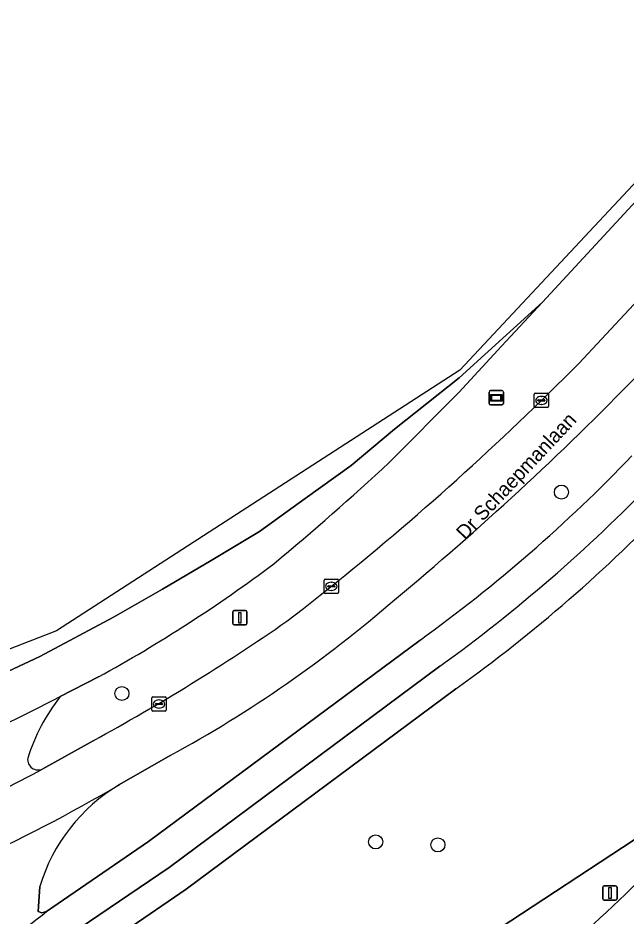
# Model space of a CAD drawing. Extents: x 161402 to 161933, y 381647 to 382315.
# Drawn here: x 161645 to 161687.4, y 382153.9 to 382216.4 of the extents above; entities that cross this region are included whole.
import ezdxf

# ---------------------------------------------------------------- set-up
doc = ezdxf.new("R2010")
doc.units = 0
for name, color, linetype in [('IMGEO_Berm_groen', 7, 'Continuous'), ('IMGEO_Boom', 7, 'Continuous'), ('IMGEO_Fietspad_open', 7, 'Continuous'), ('IMGEO_Groenvoorziening', 7, 'Continuous'), ('IMGEO_Kolk', 7, 'Continuous'), ('IMGEO_Lichtmast', 7, 'Continuous'), ('IMGEO_Openbare_ruimte_label', 7, 'Continuous'), ('IMGEO_Reclamebord', 7, 'Continuous'), ('IMGEO_Rijbaan_lokaal_gesloten', 7, 'Continuous'), ('IMGEO_Rijbaan_lokaal_open', 7, 'Continuous'), ('IMGEO_Voetpad_open', 7, 'Continuous')]:
    doc.layers.add(name, color=color, linetype=linetype)

msp = doc.modelspace()

# ---------------------------------------------------------------- linework, layer by layer
at = {"layer": 'IMGEO_Berm_groen'}
for points in [[(161689.496, 382205.269), (161681.527, 382196.651), (161678.676, 382193.568), (161675.69, 382190.338), (161670.839, 382185.46)], [(161681.452, 382189.793), (161684.055, 382192.367), (161693.624, 382202.616)], [(161646.478, 382155.909), (161646.374, 382154.17), (161646.623, 382154.084), (161646.957, 382154.172), (161654.067, 382159.041), (161672.989, 382173.086)], [(161650.566, 382170.516), (161647.909, 382169.155)], [(161646.692, 382164.118), (161650.189, 382166.07)], [(161655.565, 382165.041), (161652.03, 382163.012)]]:
    msp.add_lwpolyline(points, dxfattribs=at)
for centre, radius, start, end in [((161535.498, 382339.885), 212.859, 309.61126, 315.82773), ((161541.345, 382333.441), 200.661, 307.57252, 314.28499), ((161610.052, 382260.44), 107.665, 305.77231, 316.20072), ((161533.926, 382333.423), 201.589, 309.7406, 312.77852), ((161600.847, 382261.015), 103.257, 298.7838, 306.87243), ((161613.695, 382242.064), 87.667, 298.52876, 311.00082), ((161580.781, 382293.765), 145.339, 298.52599, 304.78691), ((161658.535, 382160.777), 13.531, 141.74802, 162.44396), ((161646.362, 382164.772), 0.733, 173.18463, 296.80226), ((161658.433, 382152.286), 12.492, 120.83452, 163.14016)]:
    msp.add_arc(centre, radius, start, end, dxfattribs=at)
at = {"layer": 'IMGEO_Boom'}
for centre in [(161682.85, 382183.401), (161652.204, 382169.365), (161669.896, 382159.022), (161674.234, 382158.814)]:
    msp.add_circle(centre, 0.489, dxfattribs=at)
at = {"layer": 'IMGEO_Fietspad_open'}
for points in [[(161672.989, 382173.086), (161654.067, 382159.041), (161646.957, 382154.172)], [(161641.929, 382148.646), (161647.103, 382151.551), (161647.127, 382151.564), (161655.489, 382157.231), (161674.382, 382171.277)]]:
    msp.add_lwpolyline(points, dxfattribs=at)
for centre, radius, start, end in [((161610.052, 382260.44), 107.665, 305.77231, 316.20072), ((161609.744, 382261.017), 110.596, 305.76448, 315.97187), ((161630.931, 382173.607), 25.19, 294.34251, 309.50932)]:
    msp.add_arc(centre, radius, start, end, dxfattribs=at)
at = {"layer": 'IMGEO_Groenvoorziening'}
for points in [[(161689.483, 382157.477), (161691.391, 382159.25), (161699.134, 382166.682), (161703.606, 382170.992), (161702.903, 382171.726), (161702.299, 382171.22), (161695.415, 382165.448), (161687.926, 382159.17), (161678.507, 382152.98), (161678.638, 382150.976), (161676.296, 382149.1), (161669.4, 382148.169), (161664.367, 382144.903), (161668.17, 382139.043)], [(161675.495, 382169.693), (161656.68, 382155.718), (161648.28, 382149.971), (161648.519, 382149.653), (161649.489, 382148.283)], [(161668.17, 382139.043), (161664.367, 382144.903), (161669.4, 382148.169), (161676.296, 382149.1), (161678.638, 382150.976), (161678.507, 382152.98), (161687.926, 382159.17), (161695.415, 382165.448)]]:
    msp.add_lwpolyline(points, dxfattribs=at)
for centre, radius, start, end in [((161611.861, 382258.34), 109.122, 305.67199, 316.21436), ((161516.254, 382334.874), 247.948, 312.0848, 314.31888)]:
    msp.add_arc(centre, radius, start, end, dxfattribs=at)
at = {"layer": 'IMGEO_Kolk'}
for p, q in [((161680.954, 382189.368), (161680.954, 382190.22)), ((161681.029, 382190.294), (161681.881, 382190.294)), ((161681.955, 382190.22), (161681.955, 382189.368)), ((161681.213, 382189.788), (161681.213, 382189.8)), ((161681.651, 382189.751), (161681.253, 382189.751)), ((161681.256, 382189.837), (161681.654, 382189.837)), ((161681.442, 382190.074), (161681.467, 382190.074)), ((161681.697, 382189.8), (161681.697, 382189.788)), ((161681.881, 382189.294), (161681.029, 382189.294)), ((161681.465, 382189.514), (161681.44, 382189.514)), ((161666.303, 382176.409), (161666.303, 382177.261)), ((161666.378, 382177.335), (161667.23, 382177.335)), ((161666.791, 382177.115), (161666.816, 382177.115)), ((161667.304, 382177.261), (161667.304, 382176.409)), ((161666.562, 382176.829), (161666.562, 382176.841)), ((161667, 382176.792), (161666.602, 382176.792)), ((161666.605, 382176.878), (161667.003, 382176.878)), ((161666.814, 382176.555), (161666.789, 382176.555)), ((161667.046, 382176.841), (161667.046, 382176.829)), ((161667.23, 382176.335), (161666.378, 382176.335)), ((161654.29, 382168.208), (161654.29, 382169.06)), ((161654.365, 382169.134), (161655.217, 382169.134)), ((161654.778, 382168.914), (161654.803, 382168.914)), ((161655.291, 382169.06), (161655.291, 382168.208)), ((161654.549, 382168.628), (161654.549, 382168.64)), ((161654.987, 382168.591), (161654.589, 382168.591)), ((161654.592, 382168.677), (161654.99, 382168.677)), ((161654.801, 382168.354), (161654.776, 382168.354)), ((161655.033, 382168.64), (161655.033, 382168.628)), ((161655.217, 382168.134), (161654.365, 382168.134))]:
    msp.add_line(p, q, dxfattribs=at)
for points in [[(161680.954, 382189.368), (161680.954, 382190.22)], [(161681.029, 382190.294), (161681.881, 382190.294)], [(161681.955, 382190.22), (161681.955, 382189.368)], [(161681.881, 382189.294), (161681.029, 382189.294)], [(161666.303, 382176.409), (161666.303, 382177.261)], [(161666.378, 382177.335), (161667.23, 382177.335)], [(161667.304, 382177.261), (161667.304, 382176.409)], [(161667.23, 382176.335), (161666.378, 382176.335)], [(161654.29, 382168.208), (161654.29, 382169.06)], [(161654.365, 382169.134), (161655.217, 382169.134)], [(161655.291, 382169.06), (161655.291, 382168.208)], [(161655.217, 382168.134), (161654.365, 382168.134)]]:
    msp.add_lwpolyline(points, dxfattribs=at)
for centre, radius, start, end in [((161681.031, 382190.218), 0.0765, 91.55205, 178.44795), ((161681.031, 382190.218), 0.0765, 91.55205, 178.44795), ((161681.879, 382190.218), 0.0765, 1.55205, 88.44795), ((161681.879, 382190.218), 0.0765, 1.55205, 88.44795), ((161681.253, 382189.797), 0.0403, 85.87752, 175.75265), ((161681.25, 382189.787), 0.0366, 178.93798, 274.71019), ((161681.654, 382189.794), 0.043, 264.86636, 352.45326), ((161681.658, 382189.799), 0.0386, 1.73085, 96.63898), ((161681.031, 382189.37), 0.0765, 181.55205, 268.44795), ((161681.031, 382189.37), 0.0765, 181.55205, 268.44795), ((161681.879, 382189.37), 0.0765, 271.55205, 358.44795), ((161681.879, 382189.37), 0.0765, 271.55205, 358.44795), ((161666.38, 382177.259), 0.0765, 91.55205, 178.44795), ((161666.38, 382177.259), 0.0765, 91.55205, 178.44795), ((161667.228, 382177.259), 0.0765, 1.55205, 88.44795), ((161667.228, 382177.259), 0.0765, 1.55205, 88.44795), ((161666.602, 382176.838), 0.0403, 85.87752, 175.75265), ((161666.599, 382176.828), 0.0366, 178.93798, 274.71019), ((161667.003, 382176.835), 0.043, 264.86636, 352.45326), ((161667.007, 382176.84), 0.0386, 1.73085, 96.63898), ((161666.38, 382176.411), 0.0765, 181.55205, 268.44795), ((161666.38, 382176.411), 0.0765, 181.55205, 268.44795), ((161667.228, 382176.411), 0.0765, 271.55205, 358.44795), ((161667.228, 382176.411), 0.0765, 271.55205, 358.44795), ((161654.367, 382169.058), 0.0765, 91.55205, 178.44795), ((161654.367, 382169.058), 0.0765, 91.55205, 178.44795), ((161655.215, 382169.058), 0.0765, 1.55205, 88.44795), ((161655.215, 382169.058), 0.0765, 1.55205, 88.44795), ((161654.589, 382168.637), 0.0403, 85.87752, 175.75265), ((161654.586, 382168.627), 0.0366, 178.93798, 274.71019), ((161654.99, 382168.634), 0.043, 264.86636, 352.45326), ((161654.994, 382168.639), 0.0386, 1.73085, 96.63898), ((161654.367, 382168.21), 0.0765, 181.55205, 268.44795), ((161654.367, 382168.21), 0.0765, 181.55205, 268.44795), ((161655.215, 382168.21), 0.0765, 271.55205, 358.44795), ((161655.215, 382168.21), 0.0765, 271.55205, 358.44795)]:
    msp.add_arc(centre, radius, start, end, dxfattribs=at)
for centre, major_axis, ratio, start_param, end_param in [((161681.441, 382189.794), (-0.387, 0.002), 0.722429, 4.712389, 7.853982), ((161681.466, 382189.794), (-0.39, 0.002), 0.717154, 1.570796, 4.712389), ((161666.79, 382176.835), (-0.387, 0.002), 0.722429, 4.712389, 7.853982), ((161666.815, 382176.835), (-0.39, 0.002), 0.717154, 1.570796, 4.712389), ((161654.777, 382168.634), (-0.387, 0.002), 0.722429, 4.712389, 7.853982), ((161654.802, 382168.634), (-0.39, 0.002), 0.717154, 1.570796, 4.712389)]:
    msp.add_ellipse(centre, major_axis=major_axis, ratio=ratio, start_param=start_param, end_param=end_param, dxfattribs=at)
at = {"layer": 'IMGEO_Lichtmast'}
for p, q in [((161659.933, 382174.247), (161659.933, 382175.047)), ((161659.933, 382175.047), (161659.933, 382174.247)), ((161660.033, 382175.147), (161660.823, 382175.147)), ((161660.823, 382175.147), (161660.033, 382175.147)), ((161660.923, 382175.047), (161660.923, 382174.247)), ((161660.923, 382174.247), (161660.923, 382175.047)), ((161660.823, 382174.147), (161660.033, 382174.147)), ((161660.033, 382174.147), (161660.823, 382174.147)), ((161685.739, 382155.063), (161685.739, 382155.863)), ((161685.739, 382155.863), (161685.739, 382155.063)), ((161685.839, 382155.963), (161686.629, 382155.963)), ((161686.629, 382155.963), (161685.839, 382155.963)), ((161686.729, 382155.863), (161686.729, 382155.063)), ((161686.729, 382155.063), (161686.729, 382155.863)), ((161686.629, 382154.963), (161685.839, 382154.963)), ((161685.839, 382154.963), (161686.629, 382154.963))]:
    msp.add_line(p, q, dxfattribs=at)
for points in [[(161660.353, 382175.022), (161660.503, 382175.022), (161660.503, 382174.272), (161660.353, 382174.272), (161660.353, 382175.022)], [(161686.159, 382155.838), (161686.309, 382155.838), (161686.309, 382155.088), (161686.159, 382155.088), (161686.159, 382155.838)]]:
    msp.add_lwpolyline(points, dxfattribs=at)
for centre, start, end in [((161660.033, 382175.047), 90, 180), ((161660.033, 382175.047), 90, 180), ((161660.823, 382175.047), 0, 90), ((161660.823, 382175.047), 360, 90), ((161660.033, 382174.247), 180, 270), ((161660.033, 382174.247), 180, 270), ((161660.823, 382174.247), 270, 0), ((161660.823, 382174.247), 270, 0), ((161685.839, 382155.863), 90, 180), ((161685.839, 382155.863), 90, 180), ((161686.629, 382155.863), 0, 90), ((161686.629, 382155.863), 360, 90), ((161685.839, 382155.063), 180, 270), ((161685.839, 382155.063), 180, 270), ((161686.629, 382155.063), 270, 0), ((161686.629, 382155.063), 270, 0)]:
    msp.add_arc(centre, 0.1, start, end, dxfattribs=at)
at = {"layer": 'IMGEO_Reclamebord'}
for p, q in [((161677.81, 382189.579), (161677.81, 382190.379)), ((161677.81, 382190.379), (161677.81, 382189.579)), ((161677.91, 382190.479), (161678.7, 382190.479)), ((161678.7, 382190.479), (161677.91, 382190.479)), ((161678.8, 382190.379), (161678.8, 382189.579)), ((161678.8, 382189.579), (161678.8, 382190.379)), ((161678.7, 382189.479), (161677.91, 382189.479)), ((161677.91, 382189.479), (161678.7, 382189.479))]:
    msp.add_line(p, q, dxfattribs=at)
for points in [[(161677.911, 382190.211), (161678.699, 382190.211), (161678.699, 382189.747), (161677.911, 382189.747), (161677.911, 382190.211)], [(161677.976, 382190.146), (161677.976, 382189.812), (161678.634, 382189.812), (161678.634, 382190.146), (161677.976, 382190.146)]]:
    msp.add_lwpolyline(points, dxfattribs=at)
for centre, start, end in [((161677.91, 382190.379), 90, 180), ((161677.91, 382190.379), 90, 180), ((161678.7, 382190.379), 0, 90), ((161678.7, 382190.379), 360, 90), ((161677.91, 382189.579), 180, 270), ((161677.91, 382189.579), 180, 270), ((161678.7, 382189.579), 270, 0), ((161678.7, 382189.579), 270, 0)]:
    msp.add_arc(centre, 0.1, start, end, dxfattribs=at)
at = {"layer": 'IMGEO_Rijbaan_lokaal_gesloten'}
for points in [[(161709.017, 382214.078), (161740.731, 382248.263), (161738.153, 382250.632), (161737.568, 382250), (161701.048, 382210.574), (161693.624, 382202.616), (161684.055, 382192.367), (161681.452, 382189.793)], [(161623.646, 382164.414), (161623.784, 382163.77), (161624.938, 382164.015), (161626.127, 382164.318), (161628.228, 382164.854), (161631.83, 382165.772), (161635.569, 382167.127), (161640.958, 382169.372), (161646.471, 382171.949), (161651.617, 382174.687), (161655.041, 382176.626), (161658.42, 382178.643), (161661.8, 382180.659), (161664.99, 382182.963), (161668.181, 382185.266), (161671.208, 382187.781), (161675.716, 382191.356), (161681.527, 382196.651), (161689.496, 382205.269), (161697.412, 382213.802), (161730.864, 382250)], [(161706.254, 382224.51), (161675.772, 382191.906), (161647.653, 382173.722), (161623.646, 382164.414)], [(161670.839, 382185.46), (161675.69, 382190.338), (161678.676, 382193.568), (161681.527, 382196.651), (161675.716, 382191.356), (161671.208, 382187.781), (161668.181, 382185.266), (161664.99, 382182.963), (161661.8, 382180.659), (161658.42, 382178.643), (161655.041, 382176.626), (161651.617, 382174.687), (161646.471, 382171.949), (161640.958, 382169.372), (161635.569, 382167.127), (161631.83, 382165.772), (161628.228, 382164.854), (161626.127, 382164.318), (161624.938, 382164.015), (161623.784, 382163.77), (161624.431, 382160.747)], [(161647.909, 382169.155), (161650.566, 382170.516)], [(161650.189, 382166.07), (161646.692, 382164.118)], [(161652.03, 382163.012), (161655.565, 382165.041)]]:
    msp.add_lwpolyline(points, dxfattribs=at)
for centre, radius, start, end in [((161535.498, 382339.885), 212.859, 309.61126, 315.82773), ((161541.345, 382333.441), 200.661, 307.57252, 314.28499), ((161533.926, 382333.423), 201.589, 309.7406, 312.77852), ((161600.847, 382261.015), 103.257, 298.7838, 306.87243), ((161613.695, 382242.064), 87.667, 298.52876, 311.00082), ((161580.781, 382293.765), 145.339, 298.52599, 304.78691), ((161602.481, 382255.416), 97.492, 287.16795, 297.77288), ((161593.034, 382262.943), 112.453, 291.45766, 298.49995), ((161594.959, 382260.14), 112.654, 288.33348, 300.43786), ((161516.254, 382334.874), 247.948, 312.0848, 314.31888)]:
    msp.add_arc(centre, radius, start, end, dxfattribs=at)
at = {"layer": 'IMGEO_Rijbaan_lokaal_open'}
msp.add_lwpolyline([(161646.957, 382154.172), (161646.623, 382154.084), (161646.374, 382154.17), (161646.478, 382155.909)], dxfattribs=at)
for centre, radius, start, end in [((161602.481, 382255.416), 97.492, 287.16795, 297.77288), ((161658.535, 382160.777), 13.531, 141.74802, 162.44396), ((161646.362, 382164.772), 0.733, 173.18463, 296.80226), ((161593.034, 382262.943), 112.453, 291.45766, 298.49995), ((161594.959, 382260.14), 112.654, 288.33348, 300.43786), ((161658.433, 382152.286), 12.492, 120.83452, 163.14016), ((161630.931, 382173.607), 25.19, 294.34251, 309.50932)]:
    msp.add_arc(centre, radius, start, end, dxfattribs=at)
at = {"layer": 'IMGEO_Voetpad_open'}
msp.add_lwpolyline([(161674.382, 382171.277), (161655.489, 382157.231), (161647.127, 382151.564), (161647.103, 382151.551), (161647.285, 382151.292), (161648.28, 382149.971), (161656.68, 382155.718), (161675.495, 382169.693)], dxfattribs=at)
for centre, radius, start, end in [((161609.744, 382261.017), 110.596, 305.76448, 315.97187), ((161611.861, 382258.34), 109.122, 305.67199, 316.21436)]:
    msp.add_arc(centre, radius, start, end, dxfattribs=at)

# ---------------------------------------------------------------- texts
at = {"layer": 'IMGEO_Openbare_ruimte_label'}
msp.add_text('Dr Schaepmanlaan', height=1, rotation=46.82409, dxfattribs=at).set_placement((161676.14, 382180.016))

doc.saveas('drawing.dxf')
